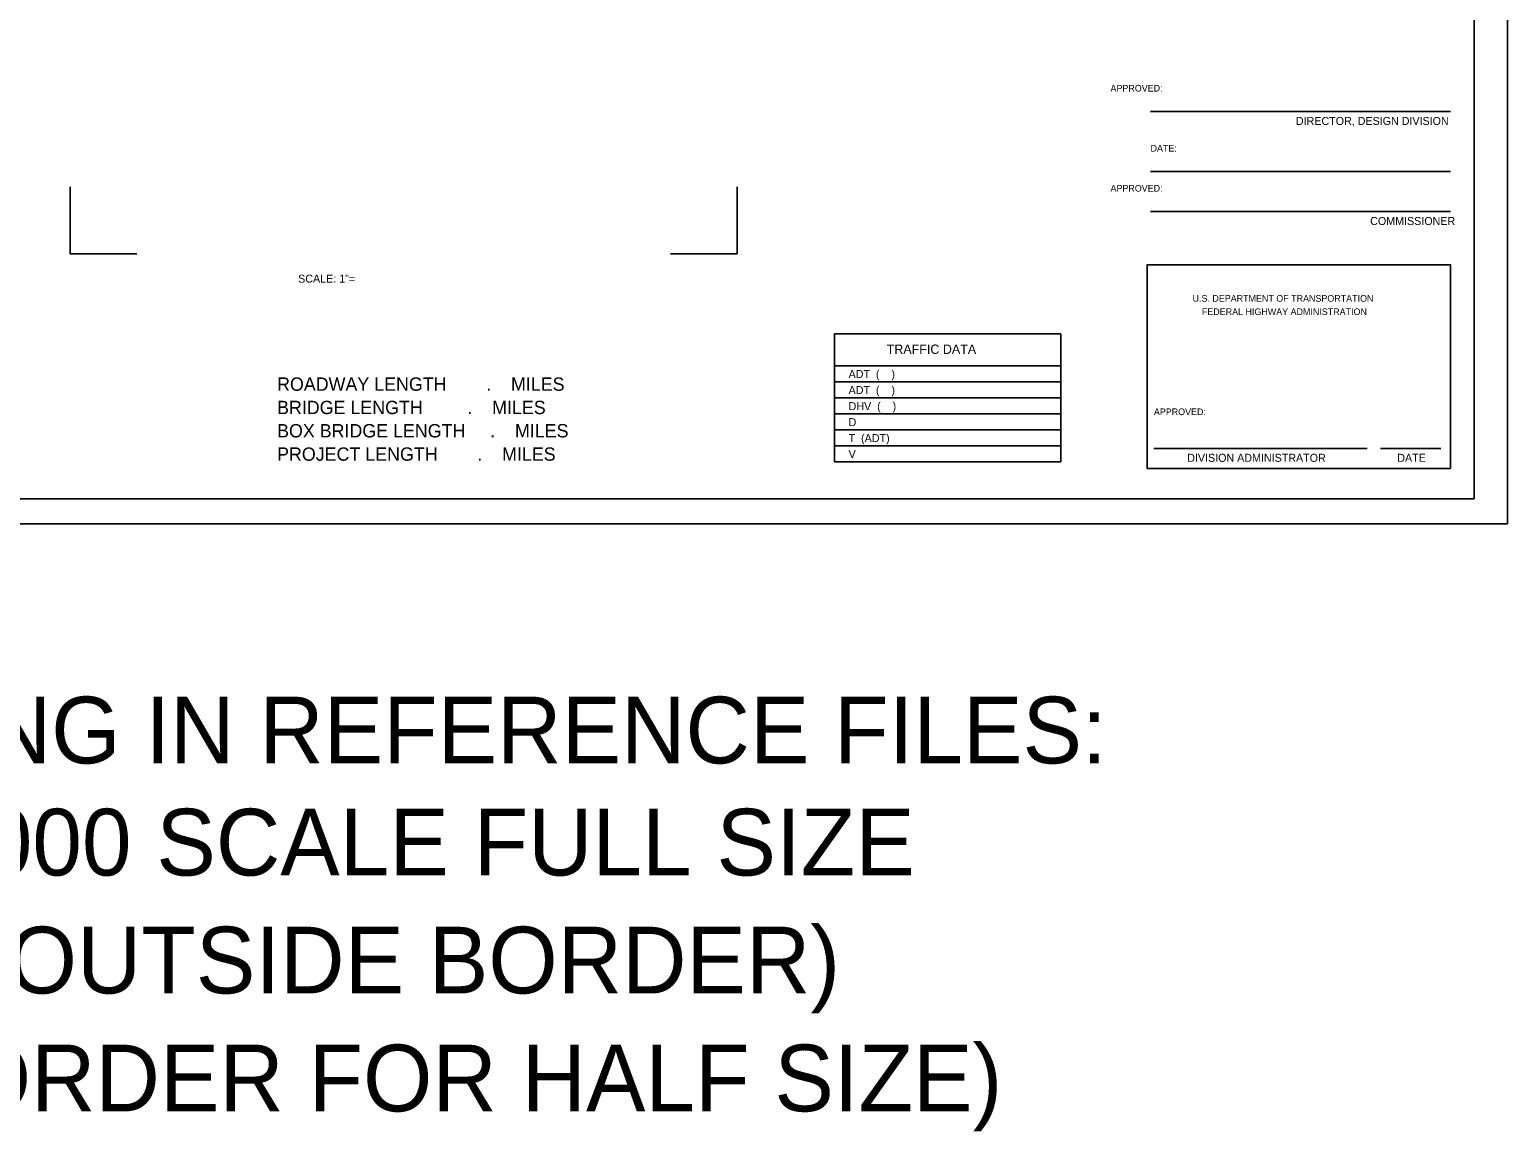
# Model space of a CAD drawing. Extents: x 1623795.1 to 1623879, y 427353.8 to 427391.8.
# Drawn here: x 1623808.9 to 1623831.06, y 427358.75 to 427375.27 of the extents above; entities that cross this region are included whole.
import ezdxf

# ---------------------------------------------------------------- set-up
doc = ezdxf.new("R2010")
doc.units = 0
for name, color, linetype in [('DESIGN - PUBLIC HEARING - Shapes', 7, 'Continuous'), ('DESIGN - SCRATCH - User 1', 7, 'Continuous'), ('DESIGN - SHEET - Corner Text', 7, 'Continuous'), ('DESIGN - SHEET - Light Grid', 7, 'Continuous'), ('DESIGN - SHEET - Linework', 7, 'Continuous')]:
    doc.layers.add(name, color=color, linetype=linetype)

msp = doc.modelspace()

# ---------------------------------------------------------------- linework, layer by layer
at = {"layer": 'DESIGN - PUBLIC HEARING - Shapes'}
msp.add_lwpolyline([(1623799.078, 427389.485), (1623830.562, 427389.485), (1623830.562, 427368.235), (1623799.079, 427368.235)], close=True, dxfattribs=at)
at = {"layer": 'DESIGN - SCRATCH - User 1'}
for p, q in [((1623809.516, 427371.908), (1623809.516, 427372.909)), ((1623819.515, 427371.908), (1623819.515, 427372.909)), ((1623809.516, 427371.908), (1623810.515, 427371.908)), ((1623819.515, 427371.908), (1623818.516, 427371.908))]:
    msp.add_line(p, q, dxfattribs=at)
at = {"layer": 'DESIGN - SHEET - Corner Text'}
for p, q in [((1623830.211, 427374.039), (1623825.712, 427374.039)), ((1623830.211, 427373.139), (1623825.712, 427373.139)), ((1623830.211, 427372.54), (1623825.712, 427372.54)), ((1623825.762, 427368.99), (1623828.961, 427368.99)), ((1623830.062, 427368.99), (1623829.162, 427368.99))]:
    msp.add_line(p, q, dxfattribs=at)
msp.add_lwpolyline([(1623830.211, 427368.689), (1623825.661, 427368.689), (1623825.661, 427371.74), (1623830.211, 427371.74)], close=True, dxfattribs=at)
at = {"layer": 'DESIGN - SHEET - Light Grid'}
for p, q in [((1623820.973, 427370.708), (1623824.369, 427370.708)), ((1623820.973, 427370.708), (1623820.973, 427368.787)), ((1623824.369, 427370.708), (1623824.369, 427368.787)), ((1623820.973, 427370.228), (1623824.369, 427370.228)), ((1623820.973, 427369.988), (1623824.369, 427369.988)), ((1623820.973, 427369.748), (1623824.369, 427369.748)), ((1623820.973, 427369.508), (1623824.369, 427369.508)), ((1623820.973, 427369.268), (1623824.369, 427369.268)), ((1623820.973, 427369.028), (1623824.369, 427369.028)), ((1623820.973, 427368.787), (1623824.369, 427368.787))]:
    msp.add_line(p, q, dxfattribs=at)
at = {"layer": 'DESIGN - SHEET - Linework'}
for p in [(1623831.063, 427389.858), (1623795.063, 427367.862)]:
    msp.add_line(p, (1623831.063, 427367.862), dxfattribs=at)
msp.add_lwpolyline([(1623799.078, 427389.485), (1623830.562, 427389.485), (1623830.562, 427368.235), (1623799.079, 427368.235), (1623799.079, 427389.236)], dxfattribs=at)

# ---------------------------------------------------------------- texts
at = {"layer": 'DESIGN - SHEET - Corner Text'}
for s, p in [('NOTE FOR SCALING IN REFERENCE FILES:', (1623797.118, 427364.268)), ('(USUALLY 1000 SCALE FULL SIZE', (1623800.548, 427362.588)), ('USING OUTSIDE BORDER)', (1623803.969, 427360.82)), ('(USE INSIDE BORDER FOR HALF SIZE)', (1623798.599, 427359.052))]:
    msp.add_text(s, height=1, dxfattribs=at).set_placement(p)
at = {"layer": 'DESIGN - SHEET - Light Grid'}
for s, height, p in [('APPROVED:', 0.1, (1623825.112, 427374.34)), ('DIRECTOR, DESIGN DIVISION', 0.11999, (1623827.891, 427373.839)), ('DATE:', 0.1, (1623825.712, 427373.44)), ('APPROVED:', 0.1, (1623825.112, 427372.84)), ('COMMISSIONER', 0.11999, (1623829.005, 427372.339)), ('SCALE: 1"=                 ', 0.11999, (1623812.932, 427371.475)), ('U.S. DEPARTMENT OF TRANSPORTATION', 0.1, (1623826.342, 427371.189)), ('FEDERAL HIGHWAY ADMINISTRATION', 0.1, (1623826.482, 427370.989)), ('TRAFFIC DATA', 0.14, (1623821.756, 427370.407)), ('ADT  (    )', 0.11999, (1623821.185, 427370.045)), ('ROADWAY LENGTH        .    MILES', 0.2, (1623812.616, 427369.854)), ('ADT  (    )', 0.11999, (1623821.185, 427369.805)), ('BRIDGE LENGTH         .    MILES', 0.2, (1623812.616, 427369.504)), ('DHV  (    )', 0.11999, (1623821.185, 427369.564)), ('D', 0.12, (1623821.185, 427369.324)), ('APPROVED:', 0.1, (1623825.762, 427369.489)), ('BOX BRIDGE LENGTH     .    MILES', 0.2, (1623812.616, 427369.155)), ('PROJECT LENGTH        .    MILES', 0.2, (1623812.616, 427368.805)), ('T  (ADT)', 0.12, (1623821.185, 427369.085)), ('V', 0.12, (1623821.185, 427368.845)), ('DIVISION ADMINISTRATOR', 0.11999, (1623826.262, 427368.789)), ('DATE', 0.12, (1623829.411, 427368.789))]:
    msp.add_text(s, height=height, dxfattribs=at).set_placement(p)

doc.saveas('drawing.dxf')
